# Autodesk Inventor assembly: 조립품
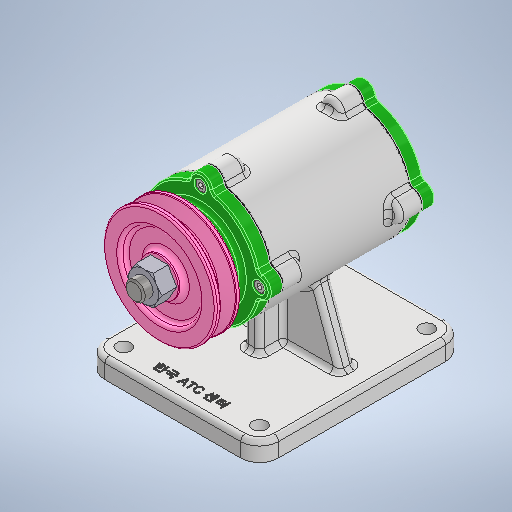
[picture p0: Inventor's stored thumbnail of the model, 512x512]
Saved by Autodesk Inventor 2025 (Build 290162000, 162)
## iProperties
Created: 2024-08
Part Number: 조립품
Document SubType Name: Assembly
Designer: deana
Author: deana
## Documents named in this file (12)
- C:\Users\deana\Desktop\740807V1009\조립품.iam
- C:\Users\deana\Desktop\740807V1009\본체.ipt
- C:\Users\deana\Desktop\740807V1009\개스킷\개스킷.ipt
- C:\Users\deana\Desktop\740807V1009\앞커버\앞커버.ipt
- C:\Users\deana\Desktop\740807V1009\뒤커버\뒤커버.ipt
- C:\Users\deana\Desktop\740807V1009\베어링 6204\베어링 6204.ipt
- C:\Users\deana\Desktop\740807V1009\오일실\오일실.ipt
- C:\Users\deana\Desktop\740807V1009\볼트 M4 x 12\볼트 M4 x 12.ipt
- C:\Users\deana\Desktop\740807V1009\축\축.ipt
- C:\Users\deana\Desktop\740807V1009\키 4 x 4\키 4 x 4.ipt
- C:\Users\deana\Desktop\740807V1009\V-벨트풀리\V-벨트풀리.ipt
- C:\Users\deana\Desktop\740807V1009\너트 M12 x 1.25\너트 M12 x 1.25.ipt
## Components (3 placed, 2 different names)
1. 개스킷:1
2. 개스킷:2
3. V-벨트풀리:1 — 각도:7
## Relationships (1: Angle 1)
- 각도:7 [Angle]: V-벨트풀리:1
